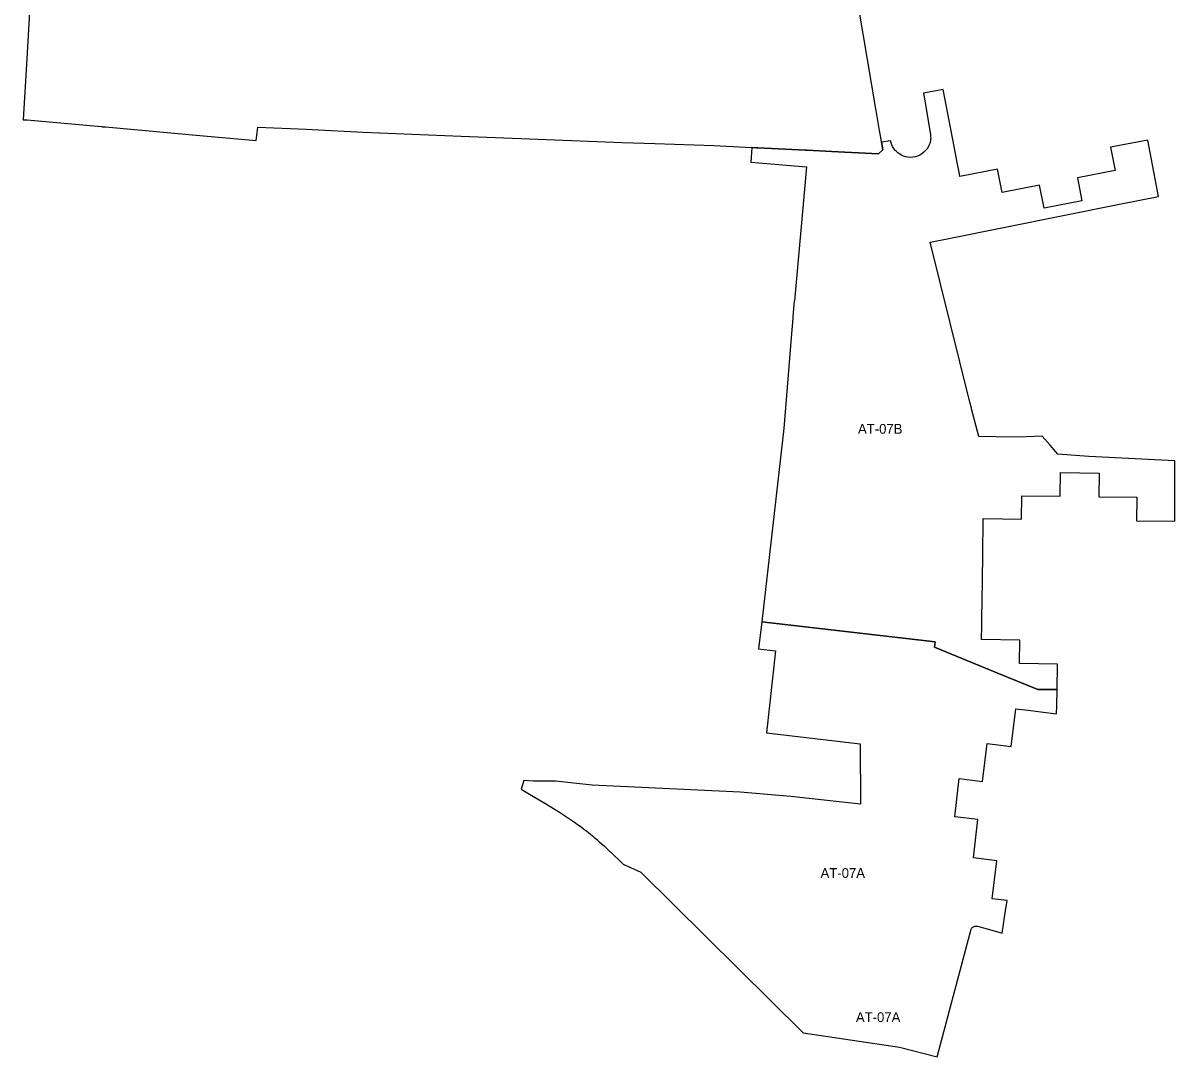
# Model space of a CAD drawing. Extents: x 428342 to 437063, y 4455780 to 4463043.
# Drawn here: x 430577 to 431164, y 4460793 to 4461320 of the extents above; entities that cross this region are included whole.
import ezdxf

# ---------------------------------------------------------------- set-up
doc = ezdxf.new("R2010")
doc.units = 0
for name, color, linetype in [('AMB_SUNC-Industriales', 7, 'Continuous'), ('AMB_SUNC-Residenciales', 7, 'Continuous'), ('AMB_SUNC-Txt', 7, 'Continuous')]:
    doc.layers.add(name, color=color, linetype=linetype)

msp = doc.modelspace()

# ---------------------------------------------------------------- linework, layer by layer
at = {"layer": 'AMB_SUNC-Industriales'}
for points in [[(430579.96, 4461325.29), (430578.45, 4461301.73), (430576.59, 4461270.46), (430578.66, 4461270.34), (430612.76, 4461267.3), (430616.75, 4461266.94), (430616.92, 4461266.92), (430618.55, 4461266.78), (430668.56, 4461262.32), (430695.47, 4461259.91), (430696.21, 4461266.74), (430720.93, 4461265.72), (430723.98, 4461265.55), (430750.05, 4461264.18), (430800, 4461262.14), (430834.69, 4461260.73), (430882.07, 4461258.77), (430898.62, 4461258.41), (430928.64, 4461257.27), (430948.04, 4461256.27)], [(430948.04, 4461256.27), (430950.52, 4461256.14), (430951.18, 4461256.11), (430975.53, 4461254.94), (430976.28, 4461254.9), (430988.7, 4461254.31), (431012.72, 4461253.15), (431014.82, 4461255.09), (431013.77, 4461261.39), (431013.19, 4461264.91), (431011.47, 4461275.22), (431011.34, 4461276.01), (431002.87, 4461326.34)]]:
    msp.add_lwpolyline(points, dxfattribs=at)
at = {"layer": 'AMB_SUNC-Residenciales'}
for points in [[(430948.04, 4461256.27), (430947.66, 4461248.81), (430976.04, 4461246.37), (430969.78, 4461178.07), (430969.67, 4461178.08), (430969.22, 4461172.18), (430968.82, 4461167.06), (430968.36, 4461161.51), (430964.48, 4461112.96), (430953.16, 4461014.5), (431041.59, 4461004.21), (431041.29, 4461001.5), (431073.04, 4460988.51), (431093.86, 4460979.99), (431103.74, 4460979.89), (431103.93, 4460992.83), (431084.47, 4460993.13), (431084.66, 4461005.14), (431065.18, 4461005.43), (431065.29, 4461012.51), (431065.36, 4461017.44), (431065.46, 4461024.54), (431065.81, 4461048.04), (431065.91, 4461055.2), (431065.98, 4461060.04), (431066.08, 4461067.1), (431085.6, 4461066.83), (431085.77, 4461078.77), (431105.24, 4461078.49), (431105.41, 4461090.52), (431125.08, 4461090.25), (431124.91, 4461078.22), (431144.4, 4461077.95), (431144.23, 4461066.03), (431163.66, 4461065.76), (431163.78, 4461096.46), (431119.82, 4461098.81), (431104.09, 4461099.92), (431100.13, 4461104.5), (431096.17, 4461109.08), (431084.22, 4461108.54), (431072.62, 4461108.73), (431063.74, 4461108.87), (431060.14, 4461123.13), (431060.07, 4461123.44), (431059.3, 4461126.52), (431038.96, 4461208.01), (431047.74, 4461209.78), (431135.47, 4461227.44), (431155.33, 4461231.37), (431149.99, 4461260.1), (431131, 4461256.39), (431133.29, 4461244.61), (431114.08, 4461240.87), (431116.36, 4461229.19), (431097.05, 4461225.42), (431094.77, 4461237.1), (431075.65, 4461233.37), (431073.34, 4461245.26), (431054.19, 4461241.53), (431053.76, 4461243.73), (431052.81, 4461248.63), (431051.9, 4461253.29), (431050.52, 4461260.37), (431045.67, 4461285.83), (431035.57, 4461284.03), (431037.11, 4461275.13), (431039.16, 4461262.72), (431039.23, 4461262.16), (431039.26, 4461261.04), (431039.23, 4461260.48), (431039.16, 4461259.92), (431038.93, 4461258.83), (431038.77, 4461258.29), (431038.35, 4461257.25), (431038.09, 4461256.75), (431037.43, 4461255.69), (431036.64, 4461254.71), (431035.74, 4461253.84), (431034.75, 4461253.07), (431033.67, 4461252.43), (431032.52, 4461251.92), (431031.32, 4461251.55), (431030.09, 4461251.33), (431028.84, 4461251.25), (431027.59, 4461251.32), (431026.35, 4461251.54), (431025.34, 4461251.89), (431024.37, 4461252.33), (431023.45, 4461252.88), (431022.59, 4461253.5), (431021.79, 4461254.22), (431021.07, 4461255), (431020.43, 4461255.86), (431019.87, 4461256.77), (431019.41, 4461257.74), (431019.05, 4461258.74), (431018.79, 4461259.78), (431014.17, 4461259.01), (431014.82, 4461255.09), (431012.72, 4461253.15), (430988.7, 4461254.25), (430976.28, 4461254.87), (430975.53, 4461254.91), (430951.18, 4461256.11), (430950.52, 4461256.14), (430948.04, 4461256.27)], [(431093.86, 4460979.99), (431073.04, 4460988.51), (431041.29, 4461001.5), (431041.59, 4461004.21), (430953.16, 4461014.5), (430951.57, 4461000.74), (430960.19, 4460999.74), (430955.56, 4460957.81), (431003.3, 4460952.24), (431003.48, 4460921.46), (430967.97, 4460925.42), (430942.09, 4460927.52), (430866.7, 4460931.24), (430847.99, 4460933.19), (430836.75, 4460933.25), (430831.82, 4460933.55), (430830.44, 4460929.05), (430834.76, 4460926.56), (430842.51, 4460921.93), (430850.03, 4460917.41), (430852.11, 4460916.07), (430855.19, 4460914.01), (430857.22, 4460912.59), (430860.22, 4460910.4)], [(430870.19, 4460902.36), (430872.93, 4460900.05), (430875.52, 4460897.59), (430876.02, 4460897.11), (430882.56, 4460890.82), (430891.48, 4460886.88), (430974.32, 4460804.91), (431023.44, 4460797.63), (431024.08, 4460797.46), (431042.52, 4460792.6), (431042.57, 4460792.59), (431059.86, 4460857.73), (431060.03, 4460858.03), (431060.24, 4460858.3), (431060.48, 4460858.55), (431060.74, 4460858.77), (431061.03, 4460858.96), (431061.35, 4460859.1), (431061.67, 4460859.21), (431062.01, 4460859.28), (431062.36, 4460859.3), (431062.7, 4460859.29), (431063.04, 4460859.23), (431070.44, 4460857.17), (431075.66, 4460855.71), (431077.23, 4460866), (431078.19, 4460872.29), (431070.63, 4460873.2), (431072.97, 4460892.64), (431061.01, 4460894.08), (431063.37, 4460913.58), (431051.5, 4460915.02), (431053.86, 4460934.5), (431065.71, 4460933.07), (431068.03, 4460952.33), (431080.28, 4460950.86), (431082.58, 4460970.11), (431090.35, 4460969.18), (431095.43, 4460968.57), (431103.38, 4460967.62), (431103.5, 4460971.7), (431103.74, 4460979.89), (431093.86, 4460979.99)]]:
    msp.add_lwpolyline(points, dxfattribs=at)
for start, end in [(50.10313, 53.29836), (48.93489, 50.10313)]:
    msp.add_arc((430759.68, 4460775.53), 168.22, start, end, dxfattribs=at)

# ---------------------------------------------------------------- texts
at = {"layer": 'AMB_SUNC-Txt'}
for s, p in [('AT-07B', (431002.2, 4461110.35)), ('AT-07A', (430983.12, 4460883.88)), ('AT-07A', (431001.14, 4460810.38))]:
    msp.add_text(s, height=5, dxfattribs=at).set_placement(p)

doc.saveas('drawing.dxf')
